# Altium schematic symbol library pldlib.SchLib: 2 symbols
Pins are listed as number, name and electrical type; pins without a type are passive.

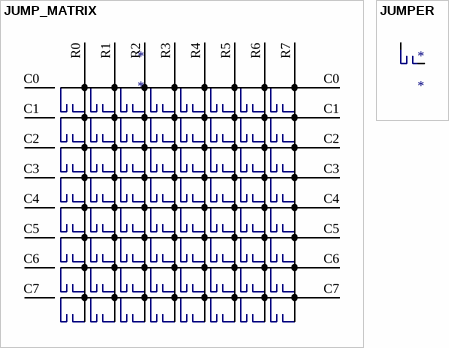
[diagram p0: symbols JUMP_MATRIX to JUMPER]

## JUMP_MATRIX
designator *
pins: C0, C0, C1, C1, C2, C2, C3, C3, C4, C4, C5, C5, C6, C6, C7, C7, R0, R1, R2, R3, R4, R5, R6, R7

## JUMPER
designator *
pins: 1, 2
